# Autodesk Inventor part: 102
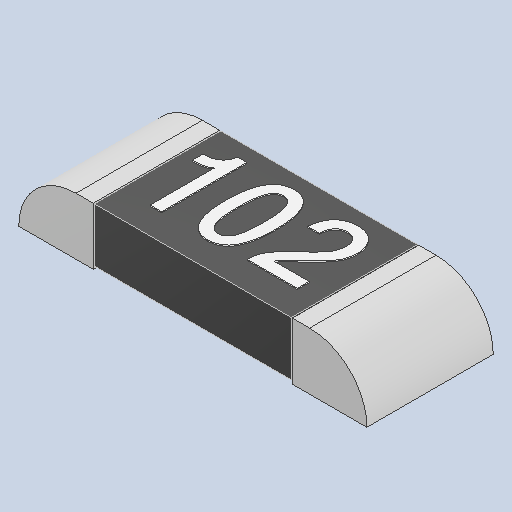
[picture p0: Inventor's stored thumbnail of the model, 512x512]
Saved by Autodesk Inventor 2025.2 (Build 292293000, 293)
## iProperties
Created: 2025-04
Part Number: 102
Material: Generic
Description: PART--DESC
Document SubType Name: Modeling
Designer: BennF
Density: 1 g/cm^3
Appearance: Default
Author: BennF
Revision Number: NONE
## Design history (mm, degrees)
feature "pin"
feature "Solid"
feature "1"
feature "0"
feature "2"
body "Solid1"
body "Solid2"
body "Solid3"
body "Solid4"
body "Solid5"
